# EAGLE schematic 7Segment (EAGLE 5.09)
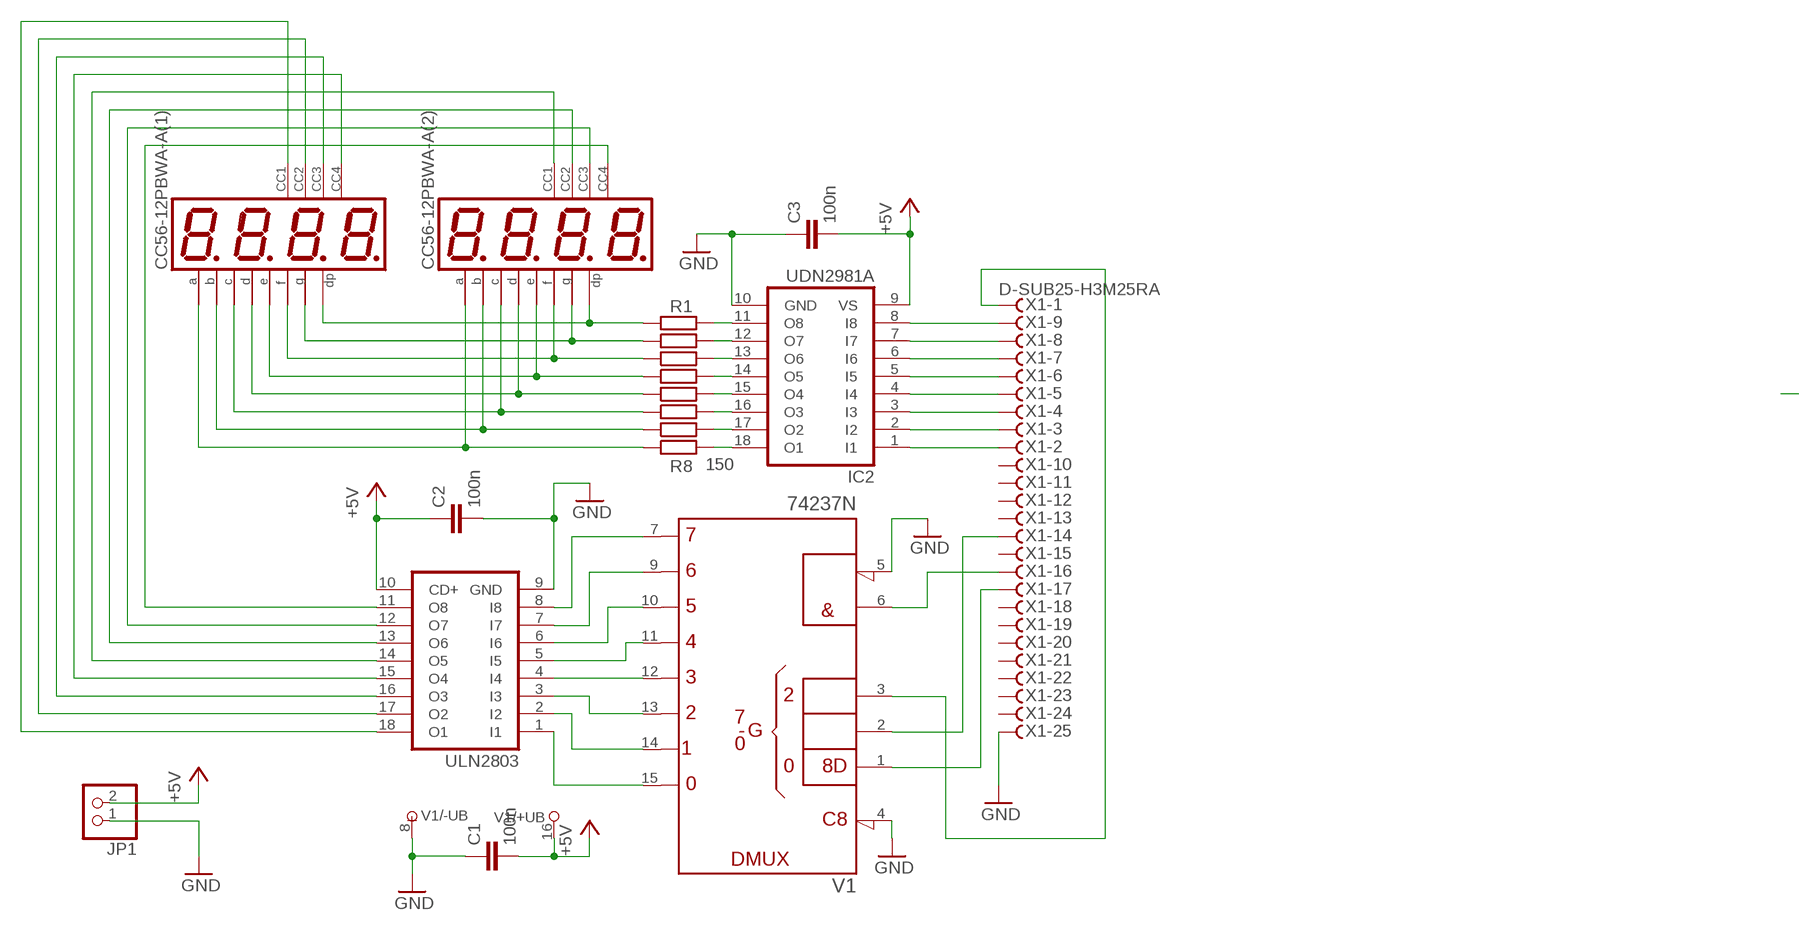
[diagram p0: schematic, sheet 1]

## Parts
C1  100n  C-EU025-025X050  [C025-025X050]
C2  100n  C-EU025-025X050  [C025-025X050]
C3  100n  C-EU025-025X050  [C025-025X050]
CC56-12PBWA-A(1)  4-FACH-7-SEGCC56-12EWA  [4-FACH-7-SEG]
CC56-12PBWA-A(2)  4-FACH-7-SEGCC56-12EWA  [4-FACH-7-SEG]
IC2  UDN2981A  [DIL18]
JP1  PINHD-1X2/90  [1X02/90]
R1  150  R-EU_0207/10  [0207/10]
R2  150  R-EU_0207/10  [0207/10]
R3  150  R-EU_0207/10  [0207/10]
R4  150  R-EU_0207/10  [0207/10]
R5  150  R-EU_0207/10  [0207/10]
R6  150  R-EU_0207/10  [0207/10]
R7  150  R-EU_0207/10  [0207/10]
R8  150  R-EU_0207/10  [0207/10]
ULN2803  ULN2803A  [DIL18]
V1  74237N  [DIL16]
X1  D-SUB25-H3M25RA  [H3M25RA]

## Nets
+5V: C1.2 C2.1 C3.2 IC2.9(VS) JP1.2 ULN2803.10(CD+) V1.16(+UB)
GND: C1.1 C2.2 C3.1 IC2.10(GND) JP1.1 ULN2803.9(GND) V1.4(!GL) V1.5(!G2) V1.8(-UB) X1.25
N$1: IC2.11(O8) R1.2
N$2: IC2.12(O7) R2.2
N$3: IC2.13(O6) R3.2
N$4: IC2.14(O5) R4.2
N$5: IC2.15(O4) R5.2
N$6: IC2.16(O3) R6.2
N$7: IC2.17(O2) R7.2
N$8: IC2.18(O1) R8.2
N$9: ULN2803.1(I1) V1.15(Y0)
N$10: ULN2803.2(I2) V1.14(Y1)
N$11: ULN2803.3(I3) V1.13(Y2)
N$12: ULN2803.4(I4) V1.12(Y3)
N$13: ULN2803.5(I5) V1.11(Y4)
N$14: ULN2803.6(I6) V1.10(Y5)
N$15: ULN2803.7(I7) V1.9(Y6)
N$16: ULN2803.8(I8) V1.7(Y7)
N$17: CC56-12PBWA-A(1).P3(DP) CC56-12PBWA-A(2).P3(DP) R1.1
N$18: CC56-12PBWA-A(1).P5(G) CC56-12PBWA-A(2).P5(G) R2.1
N$19: CC56-12PBWA-A(1).P10(F) CC56-12PBWA-A(2).P10(F) R3.1
N$20: CC56-12PBWA-A(1).P1(E) CC56-12PBWA-A(2).P1(E) R4.1
N$21: CC56-12PBWA-A(1).P2(D) CC56-12PBWA-A(2).P2(D) R5.1
N$22: CC56-12PBWA-A(1).P4(C) CC56-12PBWA-A(2).P4(C) R6.1
N$23: CC56-12PBWA-A(1).P7(B) CC56-12PBWA-A(2).P7(B) R7.1
N$24: CC56-12PBWA-A(1).P11(A) CC56-12PBWA-A(2).P11(A) R8.1
N$25: CC56-12PBWA-A(2).P6(CC) ULN2803.11(O8)
N$26: CC56-12PBWA-A(2).P8(CC) ULN2803.12(O7)
N$27: CC56-12PBWA-A(2).P9(CC) ULN2803.13(O6)
N$28: CC56-12PBWA-A(2).P12(CC) ULN2803.14(O5)
N$29: CC56-12PBWA-A(1).P12(CC) ULN2803.18(O1)
N$30: CC56-12PBWA-A(1).P6(CC) ULN2803.15(O4)
N$31: CC56-12PBWA-A(1).P8(CC) ULN2803.16(O3)
N$32: CC56-12PBWA-A(1).P9(CC) ULN2803.17(O2)
N$33: IC2.8(I8) X1.9
N$35: IC2.7(I7) X1.8
N$36: IC2.6(I6) X1.7
N$37: IC2.5(I5) X1.6
N$38: IC2.4(I4) X1.5
N$39: IC2.3(I3) X1.4
N$40: IC2.2(I2) X1.3
N$41: IC2.1(I1) X1.2
SUB25-D1: V1.3(C) X1.1
SUB25-D14: V1.2(B) X1.14
SUB25-D16: V1.6(G1) X1.16
SUB25-D17: V1.1(A) X1.17
Unconnected: X1.10 X1.11 X1.12 X1.13 X1.15 X1.18 X1.19 X1.20 X1.21 X1.22 X1.23 X1.24

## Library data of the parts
C1-C3 = rcl:C-EU: CAPACITOR, European symbol
CC56-12PBWA-A(1) CC56-12PBWA-A(2) = MikeLib:4-FACH-7-SEG
IC2 = uln-udn:UDN298*: DRIVER ARRAY Source: Allegro Microsystems Inc. / UDN2981-UDN2984.pdf
JP1 = pinhead:PINHD-1X2: PIN HEADER
R1-R8 = rcl:R-EU_: RESISTOR, European symbol
ULN2803 = uln-udn:ULN2803A: DRIVER ARRAY
V1 = 74ttl-din:74*237: 1 of 8 noninverting DECODER/DEMULTIPLEXER, latches
X1 = con-thomas-betts:D-SUB25-: D-Subminiatur Connector Source: Electronioc Interconnects European Edition 1998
